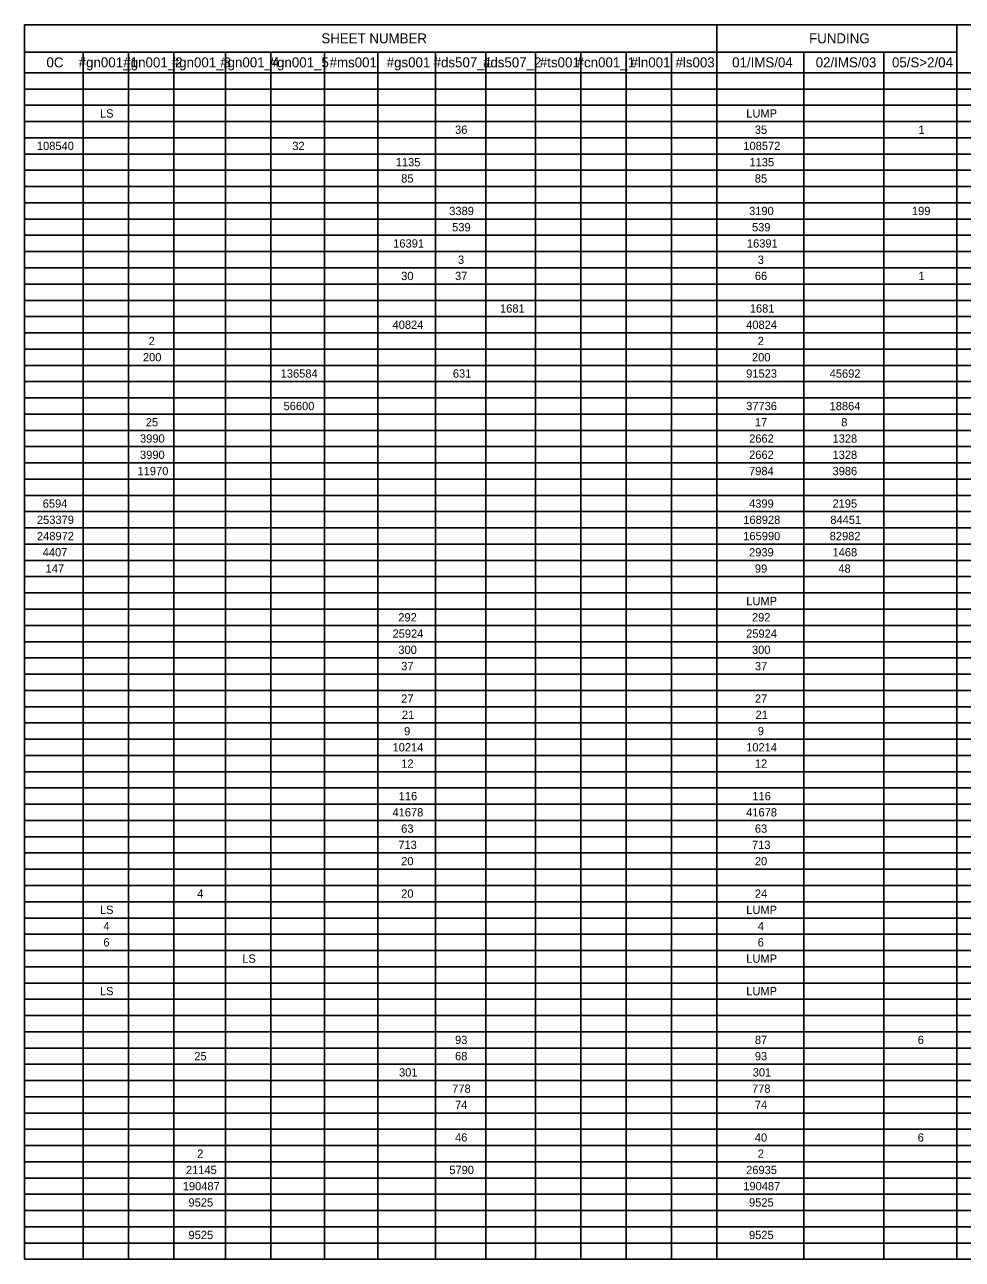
# Model space of a CAD drawing. Extents: x -542 to 295, y -281 to 32.
# Drawn here: x -541.71 to -525.86, y -10.44 to 10.41 of the extents above; entities that cross this region are included whole.
import ezdxf

# ---------------------------------------------------------------- set-up
doc = ezdxf.new("R2010")
doc.units = 0
doc.layers.add('SH_Data', color=7, linetype='Continuous')
doc.layers.add('SH_Text', color=7, linetype='Continuous')

msp = doc.modelspace()

# ---------------------------------------------------------------- linework, layer by layer
at = {"layer": 'SH_Data'}
for p, q in [((-541.706, 10.407), (-511.206, 10.407)), ((-541.706, 10.407), (-541.706, -10.444)), ((-530.01, 10.407), (-530.01, -10.444)), ((-525.956, 10.407), (-525.956, -10.444)), ((-541.706, 9.946), (-525.956, 9.946)), ((-540.716, 9.946), (-540.716, -10.444)), ((-539.95, 9.946), (-539.95, -10.444)), ((-539.184, 9.946), (-539.184, -10.444)), ((-538.311, 9.946), (-538.311, -10.444)), ((-537.545, 9.946), (-537.545, -10.444)), ((-536.64, 9.946), (-536.64, -10.444)), ((-535.736, 9.946), (-535.736, -10.444)), ((-534.767, 9.946), (-534.767, -10.444)), ((-533.916, 9.946), (-533.916, -10.444)), ((-533.075, 9.946), (-533.075, -10.444)), ((-532.309, 9.946), (-532.309, -10.444)), ((-531.543, 9.946), (-531.543, -10.444)), ((-530.776, 9.946), (-530.776, -10.444)), ((-528.542, 9.946), (-528.542, -10.444)), ((-527.19, 9.946), (-527.19, -10.444)), ((-541.706, 9.595), (-511.206, 9.595)), ((-541.706, 9.32), (-511.206, 9.32)), ((-541.706, 9.046), (-511.206, 9.046)), ((-541.706, 8.771), (-511.206, 8.771)), ((-541.706, 8.497), (-511.206, 8.497)), ((-541.706, 8.222), (-511.206, 8.222)), ((-541.706, 7.948), (-511.206, 7.948)), ((-541.706, 7.673), (-511.206, 7.673)), ((-541.706, 7.399), (-511.206, 7.399)), ((-541.706, 7.124), (-511.206, 7.124)), ((-541.706, 6.85), (-511.206, 6.85)), ((-541.706, 6.575), (-511.206, 6.575)), ((-541.706, 6.301), (-511.206, 6.301)), ((-541.706, 6.026), (-511.206, 6.026)), ((-541.706, 5.752), (-511.206, 5.752)), ((-541.706, 5.477), (-511.206, 5.477)), ((-541.706, 5.203), (-511.206, 5.203)), ((-541.706, 4.928), (-511.206, 4.928)), ((-541.706, 4.654), (-511.206, 4.654)), ((-541.706, 4.379), (-511.206, 4.379)), ((-541.706, 4.105), (-511.206, 4.105)), ((-541.706, 3.83), (-511.206, 3.83)), ((-541.706, 3.556), (-511.206, 3.556)), ((-541.706, 3.281), (-511.206, 3.281)), ((-541.706, 3.007), (-511.206, 3.007)), ((-541.706, 2.732), (-511.206, 2.732)), ((-541.706, 2.458), (-511.206, 2.458)), ((-541.706, 2.183), (-511.206, 2.183)), ((-541.706, 1.909), (-511.206, 1.909)), ((-541.706, 1.634), (-511.206, 1.634)), ((-541.706, 1.36), (-511.206, 1.36)), ((-541.706, 1.085), (-511.206, 1.085)), ((-541.706, 0.811), (-511.206, 0.811)), ((-541.706, 0.536), (-511.206, 0.536)), ((-541.706, 0.262), (-511.206, 0.262)), ((-541.706, -0.013), (-511.206, -0.013)), ((-541.706, -0.287), (-511.206, -0.287)), ((-541.706, -0.562), (-511.206, -0.562)), ((-541.706, -0.836), (-511.206, -0.836)), ((-541.706, -1.111), (-511.206, -1.111)), ((-541.706, -1.385), (-511.206, -1.385)), ((-541.706, -1.66), (-511.206, -1.66)), ((-541.706, -1.935), (-511.206, -1.935)), ((-541.706, -2.209), (-511.206, -2.209)), ((-541.706, -2.484), (-511.206, -2.484)), ((-541.706, -2.758), (-511.206, -2.758)), ((-541.706, -3.033), (-511.206, -3.033)), ((-541.706, -3.307), (-511.206, -3.307)), ((-541.706, -3.582), (-511.206, -3.582)), ((-541.706, -3.856), (-511.206, -3.856)), ((-541.706, -4.131), (-511.206, -4.131)), ((-541.706, -4.405), (-511.206, -4.405)), ((-541.706, -4.68), (-511.206, -4.68)), ((-541.706, -4.954), (-511.206, -4.954)), ((-541.706, -5.229), (-511.206, -5.229)), ((-541.706, -5.503), (-511.206, -5.503)), ((-541.706, -5.778), (-511.206, -5.778)), ((-541.706, -6.052), (-511.206, -6.052)), ((-541.706, -6.327), (-511.206, -6.327)), ((-541.706, -6.601), (-511.206, -6.601)), ((-541.706, -6.876), (-511.206, -6.876)), ((-541.706, -7.15), (-511.206, -7.15)), ((-541.706, -7.425), (-511.206, -7.425)), ((-541.706, -7.699), (-511.206, -7.699)), ((-541.706, -7.974), (-511.206, -7.974)), ((-541.706, -8.248), (-511.206, -8.248)), ((-541.706, -8.523), (-511.206, -8.523)), ((-541.706, -8.797), (-511.206, -8.797)), ((-541.706, -9.072), (-511.206, -9.072)), ((-541.706, -9.346), (-511.206, -9.346)), ((-541.706, -9.621), (-511.206, -9.621)), ((-541.706, -9.895), (-511.206, -9.895)), ((-541.706, -10.17), (-511.206, -10.17)), ((-541.706, -10.444), (-511.206, -10.444))]:
    msp.add_line(p, q, dxfattribs=at)

# ---------------------------------------------------------------- texts
at = {"layer": 'SH_Text'}
for s, height, p in [('SHEET NUMBER', 0.168, (-536.693, 10.093)), ('FUNDING', 0.168, (-528.452, 10.093)), ('0C', 0.168, (-541.338, 9.687)), ('#gn001_1', 0.168, (-540.793, 9.687)), ('#gn001_2', 0.168, (-540.038, 9.687)), ('#gn001_3', 0.168, (-539.22, 9.687)), ('#gn001_4', 0.168, (-538.402, 9.687)), ('#gn001_5', 0.168, (-537.566, 9.687)), ('#ms001', 0.168, (-536.554, 9.687)), ('#gs001', 0.168, (-535.589, 9.687)), ('#ds507_1', 0.168, (-534.796, 9.687)), ('#ds507_2', 0.168, (-533.962, 9.687)), ('#ts001', 0.168, (-533.001, 9.687)), ('#cn001_1', 0.168, (-532.38, 9.687)), ('#ln001', 0.168, (-531.469, 9.687)), ('#ls003', 0.168, (-530.709, 9.687)), ('01/IMS/04', 0.168, (-529.752, 9.687)), ('02/IMS/03', 0.168, (-528.34, 9.687)), ('05/S>2/04', 0.168, (-527.052, 9.687)), ('LS', 0.14, (-540.434, 8.839)), ('LUMP', 0.14, (-529.514, 8.839)), ('36', 0.14, (-534.434, 8.564)), ('35', 0.14, (-529.369, 8.564)), ('1', 0.14, (-526.605, 8.564)), ('108540', 0.14, (-541.499, 8.29)), ('32', 0.14, (-537.184, 8.29)), ('108572', 0.14, (-529.563, 8.29)), ('1135', 0.14, (-535.436, 8.015)), ('1135', 0.14, (-529.46, 8.015)), ('85', 0.14, (-535.344, 7.741)), ('85', 0.14, (-529.369, 7.741)), ('3389', 0.14, (-534.532, 7.192)), ('3190', 0.14, (-529.466, 7.192)), ('199', 0.14, (-526.714, 7.192)), ('539', 0.14, (-534.483, 6.917)), ('539', 0.14, (-529.417, 6.917)), ('16391', 0.14, (-535.479, 6.643)), ('16391', 0.14, (-529.503, 6.643)), ('3', 0.14, (-534.385, 6.368)), ('3', 0.14, (-529.319, 6.368)), ('30', 0.14, (-535.344, 6.094)), ('37', 0.14, (-534.434, 6.094)), ('66', 0.14, (-529.368, 6.094)), ('1', 0.14, (-526.605, 6.094)), ('1681', 0.14, (-533.674, 5.545)), ('1681', 0.14, (-529.454, 5.545)), ('40824', 0.14, (-535.49, 5.27)), ('40824', 0.14, (-529.515, 5.27)), ('2', 0.14, (-539.61, 4.995)), ('2', 0.14, (-529.319, 4.995)), ('200', 0.14, (-539.708, 4.721)), ('200', 0.14, (-529.417, 4.721)), ('136584', 0.14, (-537.38, 4.446)), ('631', 0.14, (-534.471, 4.446)), ('91523', 0.14, (-529.515, 4.446)), ('45692', 0.14, (-528.104, 4.446)), ('56600', 0.14, (-537.331, 3.897)), ('37736', 0.14, (-529.515, 3.897)), ('18864', 0.14, (-528.105, 3.897)), ('25', 0.14, (-539.66, 3.623)), ('17', 0.14, (-529.368, 3.623)), ('8', 0.14, (-527.909, 3.623)), ('3990', 0.14, (-539.757, 3.348)), ('2662', 0.14, (-529.465, 3.348)), ('1328', 0.14, (-528.056, 3.348)), ('3990', 0.14, (-539.757, 3.074)), ('2662', 0.14, (-529.465, 3.074)), ('1328', 0.14, (-528.056, 3.074)), ('11970', 0.14, (-539.799, 2.799)), ('7984', 0.14, (-529.466, 2.799)), ('3986', 0.14, (-528.056, 2.799)), ('6594', 0.14, (-541.401, 2.25)), ('4399', 0.14, (-529.466, 2.25)), ('2195', 0.14, (-528.057, 2.25)), ('253379', 0.14, (-541.499, 1.976)), ('168928', 0.14, (-529.564, 1.976)), ('84451', 0.14, (-528.093, 1.976)), ('248972', 0.14, (-541.498, 1.701)), ('165990', 0.14, (-529.564, 1.701)), ('82982', 0.14, (-528.104, 1.701)), ('4407', 0.14, (-541.401, 1.427)), ('2939', 0.14, (-529.466, 1.427)), ('1468', 0.14, (-528.056, 1.427)), ('147', 0.14, (-541.352, 1.152)), ('99', 0.14, (-529.368, 1.152)), ('48', 0.14, (-527.958, 1.152)), ('LUMP', 0.14, (-529.514, 0.603)), ('292', 0.14, (-535.392, 0.329)), ('292', 0.14, (-529.417, 0.329)), ('25924', 0.14, (-535.49, 0.054)), ('25924', 0.14, (-529.515, 0.054)), ('300', 0.14, (-535.392, -0.22)), ('300', 0.14, (-529.417, -0.22)), ('37', 0.14, (-535.344, -0.495)), ('37', 0.14, (-529.368, -0.495)), ('27', 0.14, (-535.344, -1.044)), ('27', 0.14, (-529.368, -1.044)), ('21', 0.14, (-535.332, -1.318)), ('21', 0.14, (-529.356, -1.318)), ('9', 0.14, (-535.295, -1.593)), ('9', 0.14, (-529.319, -1.593)), ('10214', 0.14, (-535.49, -1.867)), ('10214', 0.14, (-529.515, -1.867)), ('12', 0.14, (-535.343, -2.142)), ('12', 0.14, (-529.368, -2.142)), ('116', 0.14, (-535.386, -2.691)), ('116', 0.14, (-529.411, -2.691)), ('41678', 0.14, (-535.491, -2.965)), ('41678', 0.14, (-529.515, -2.965)), ('63', 0.14, (-535.344, -3.24)), ('63', 0.14, (-529.368, -3.24)), ('713', 0.14, (-535.393, -3.514)), ('713', 0.14, (-529.417, -3.514)), ('20', 0.14, (-535.344, -3.789)), ('20', 0.14, (-529.368, -3.789)), ('4', 0.14, (-538.791, -4.338)), ('20', 0.14, (-535.344, -4.338)), ('24', 0.14, (-529.368, -4.338)), ('LS', 0.14, (-540.434, -4.612)), ('LUMP', 0.14, (-529.514, -4.612)), ('4', 0.14, (-540.376, -4.887)), ('4', 0.14, (-529.319, -4.887)), ('6', 0.14, (-540.376, -5.161)), ('6', 0.14, (-529.319, -5.161)), ('LS', 0.14, (-538.029, -5.436)), ('LUMP', 0.14, (-529.514, -5.436)), ('LS', 0.14, (-540.434, -5.985)), ('LUMP', 0.14, (-529.514, -5.985)), ('93', 0.14, (-534.434, -6.808)), ('87', 0.14, (-529.368, -6.808)), ('6', 0.14, (-526.616, -6.808)), ('25', 0.14, (-538.84, -7.083)), ('68', 0.14, (-534.434, -7.083)), ('93', 0.14, (-529.368, -7.083)), ('301', 0.14, (-535.381, -7.357)), ('301', 0.14, (-529.405, -7.357)), ('778', 0.14, (-534.483, -7.632)), ('778', 0.14, (-529.417, -7.632)), ('74', 0.14, (-534.434, -7.906)), ('74', 0.14, (-529.368, -7.906)), ('46', 0.14, (-534.434, -8.456)), ('40', 0.14, (-529.368, -8.456)), ('6', 0.14, (-526.616, -8.456)), ('2', 0.14, (-538.79, -8.73)), ('2', 0.14, (-529.319, -8.73)), ('21145', 0.14, (-538.981, -9.005)), ('5790', 0.14, (-534.531, -9.005)), ('26935', 0.14, (-529.516, -9.005)), ('190487', 0.14, (-539.035, -9.279)), ('190487', 0.14, (-529.564, -9.279)), ('9525', 0.14, (-538.938, -9.554)), ('9525', 0.14, (-529.467, -9.554)), ('9525', 0.14, (-538.938, -10.103)), ('9525', 0.14, (-529.467, -10.103))]:
    msp.add_text(s, height=height, dxfattribs=at).set_placement(p)

doc.saveas('drawing.dxf')
